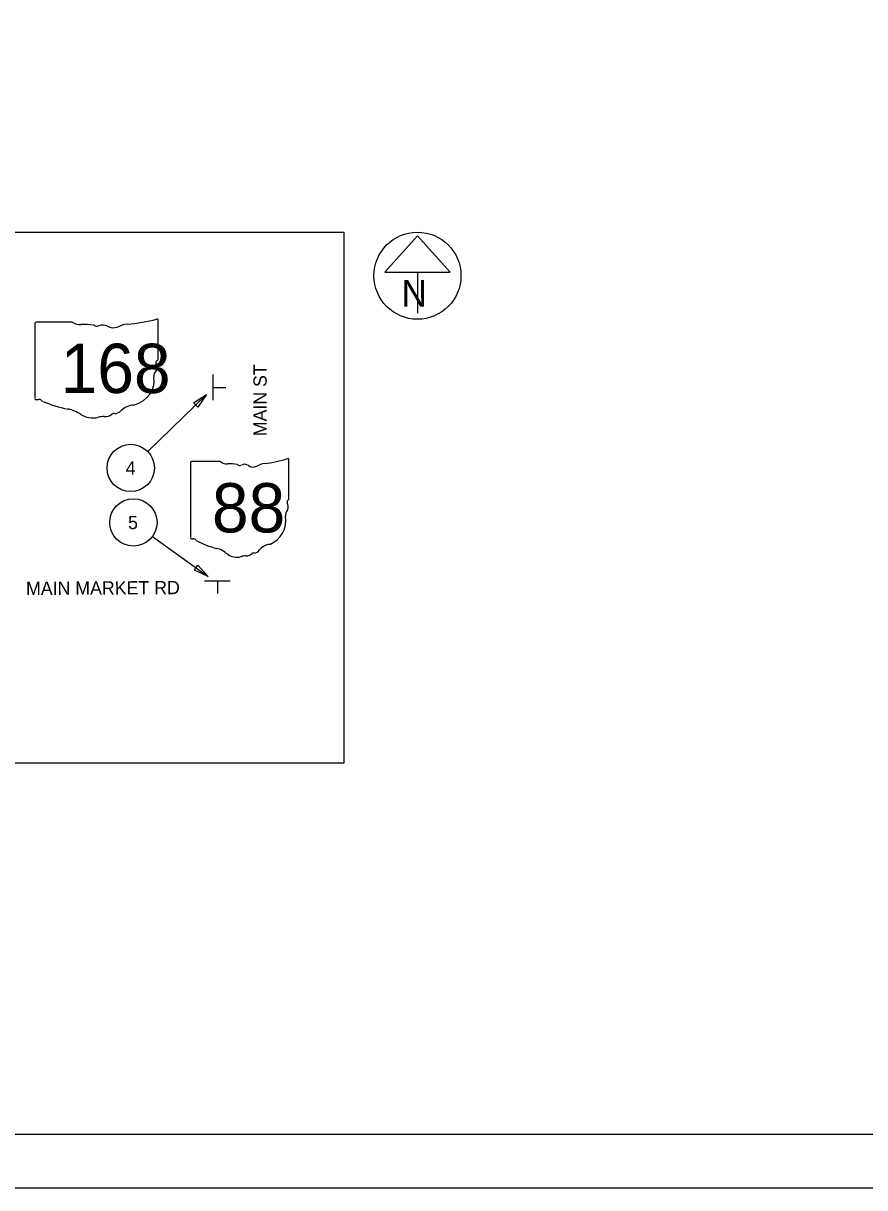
# Model space of a CAD drawing. Extents: x -0.3 to 34, y 0 to 22.
# Drawn here: x 18.15 to 26.07, y 0 to 10.97 of the extents above; entities that cross this region are included whole.
import ezdxf

# ---------------------------------------------------------------- set-up
doc = ezdxf.new("R2010")
doc.units = 0
for name, color, linetype in [('GM_X_Adjacent_County_Text', 7, 'Continuous'), ('GM_X_County', 7, 'Continuous'), ('GM_X_County_Subdivision', 7, 'Continuous'), ('GM_X_County_Subdivision_Text', 7, 'Continuous'), ('GM_X_Minor_River_Text', 7, 'Continuous'), ('GM_X_Section', 7, 'Continuous')]:
    doc.layers.add(name, color=color, linetype=linetype)

msp = doc.modelspace()

# ---------------------------------------------------------------- linework, layer by layer
at = {"layer": 'GM_X_Adjacent_County_Text'}
for p, q in [((21.86, 8.964), (21.552, 8.623)), ((22.168, 8.623), (21.86, 8.964)), ((21.552, 8.623), (22.168, 8.623)), ((21.86, 8.623), (21.86, 8.236)), ((19.32, 6.935), (19.872, 7.471)), ((19.365, 6.135), (19.889, 5.757))]:
    msp.add_line(p, q, dxfattribs=at)
for points in [[(16.167, 9), (21.167, 9), (21.167, 4), (16.167, 4)], [(19.791, 7.353), (19.752, 7.393), (19.872, 7.471)], [(19.759, 5.816), (19.792, 5.862), (19.889, 5.757)]]:
    msp.add_lwpolyline(points, close=True, dxfattribs=at)
for centre, radius in [((21.86, 8.59), 0.41), ((19.159, 6.779), 0.223), ((19.184, 6.266), 0.223)]:
    msp.add_circle(centre, radius, dxfattribs=at)
at = {"layer": 'GM_X_County'}
msp.add_lwpolyline([(1.5, 21.5), (33.5, 21.5), (33.5, 0.5), (1.5, 0.5)], close=True, dxfattribs=at)
at = {"layer": 'GM_X_County_Subdivision'}
for p, q in [((18.257, 8.139), (18.257, 7.435)), ((18.608, 8.152), (18.269, 8.152)), ((19.417, 7.8), (19.417, 8.169)), ((19.417, 7.801), (19.417, 7.8)), ((19.722, 6.827), (19.722, 6.123)), ((20.003, 6.839), (19.731, 6.839)), ((20.65, 6.488), (20.65, 6.857)), ((20.65, 6.488), (20.65, 6.488))]:
    msp.add_line(p, q, dxfattribs=at)
for centre, radius, start, end in [((19.733, 6.829), 0.0108, 98.1301, 188.1301), ((20.068, 6.921), 0.104, 231.6195, 271.1119), ((20.102, 6.444), 0.374, 80.4867, 94.9883), ((20.187, 6.832), 0.0301, 219.7921, 297.1024), ((20.232, 6.751), 0.0626, 54.4667, 119.1411), ((20.312, 6.863), 0.0753, 233.8562, 294.8282), ((20.445, 6.624), 0.198, 97.3462, 120.7689), ((20.32, 7.8), 0.984, 275.8445, 288.9065), ((20.64, 6.858), 0.0103, 351.8621, 97.738), ((20.648, 6.461), 0.016, 107.944, 210.337), ((20.639, 6.487), 0.0111, 289.6038, 7.7341), ((20.687, 6.334), 0.0698, 136.8065, 186.9296), ((20.546, 6.415), 0.096, 340.033, 23.6496), ((20.375, 6.287), 0.246, 292.3089, 8.9858), ((19.733, 6.121), 0.0108, 171.9584, 258.3066), ((19.735, 6.193), 0.0828, 267.339, 280.6039), ((19.751, 6.082), 0.0298, 29.7484, 93.2717), ((20.128, 6.715), 0.711, 240.4129, 257.1985), ((20.479, 5.925), 0.135, 94.4031, 142.5768), ((19.916, 5.806), 0.222, 47.1842, 75.836), ((20.157, 6.079), 0.141, 230.7004, 286.2918), ((20.239, 5.835), 0.116, 85.6951, 111.2099), ((20.249, 6.026), 0.0752, 268.777, 315.5493), ((20.317, 5.958), 0.0212, 65.7517, 132.6484), ((20.308, 6.054), 0.0795, 282.8732, 323.2771)]:
    msp.add_arc(centre, radius, start, end, dxfattribs=at)
for centre, major_axis, start_param, end_param in [((18.27, 8.141), (0.0134, 0), 1.712693, 3.28349), ((18.689, 8.233), (0.13, 0), 4.042523, 4.731795), ((18.732, 7.756), (0.468, 0), 1.404758, 1.657858), ((18.839, 8.145), (0.0376, 0), 3.836095, 5.185415), ((18.894, 8.063), (0.0782, 0), 0.950623, 2.079405), ((19.161, 7.936), (0.248, 0), 1.699011, 2.107814), ((19.004, 9.112), (1.23, 0), 4.814394, 5.042369), ((19.404, 8.171), (0.0129, 0), 6.141152, 7.989035), ((18.995, 8.175), (0.0941, 0), 4.081561, 5.145723), ((19.414, 7.773), (0.02, 0), 1.883978, 3.671073), ((19.403, 7.799), (0.0138, 0), 5.05454, 6.418171), ((19.463, 7.646), (0.0873, 0), 2.387724, 3.262537), ((19.287, 7.727), (0.12, 0), 5.934695, 6.695948), ((19.073, 7.599), (0.308, 0), 5.101752, 6.440018), ((18.27, 7.433), (0.0136, 0), 3.00124, 4.508301), ((18.273, 7.506), (0.103, 0), 4.665946, 4.897461), ((18.294, 7.394), (0.0373, 0), 0.519207, 1.627899), ((18.765, 8.027), (0.888, 0), 4.195997, 4.488961), ((19.203, 7.237), (0.169, 0), 1.647645, 2.488434), ((18.5, 7.119), (0.278, 0), 0.823519, 1.323587), ((18.801, 7.391), (0.176, 0), 4.026481, 4.996735), ((18.902, 7.147), (0.145, 0), 1.495662, 1.94098), ((18.915, 7.338), (0.094, 0), 4.691044, 5.507374), ((19, 7.27), (0.0265, 0), 1.147584, 2.315152), ((18.989, 7.367), (0.0994, 0), 4.937069, 5.64225)]:
    msp.add_ellipse(centre, major_axis=major_axis, ratio=0.8, start_param=start_param, end_param=end_param, dxfattribs=at)
at = {"layer": 'GM_X_County_Subdivision_Text'}
msp.add_circle((21.86, 8.59), 0.41, dxfattribs=at)
at = {"layer": 'GM_X_Minor_River_Text'}
for p, q in [((19.935, 7.418), (19.935, 7.658)), ((19.935, 7.538), (20.055, 7.538)), ((19.855, 5.717), (20.095, 5.717)), ((19.975, 5.717), (19.975, 5.597))]:
    msp.add_line(p, q, dxfattribs=at)
at = {"layer": 'GM_X_Section'}
msp.add_lwpolyline([(0, 0), (34, 0), (34, 22), (0, 22)], close=True, dxfattribs=at)

# ---------------------------------------------------------------- texts
at = {"layer": 'GM_X_Adjacent_County_Text'}
for s, height, p in [('N', 0.25, (21.709, 8.299)), ('4', 0.125, (19.112, 6.717)), ('5', 0.125, (19.134, 6.203))]:
    msp.add_text(s, height=height, dxfattribs=at).set_placement(p)
for s, rotation, p in [('MAIN ST', 90, (20.44, 7.078)), ('MAIN MARKET RD', 0.3376, (18.173, 5.582))]:
    msp.add_text(s, height=0.125, rotation=rotation, dxfattribs=at).set_placement(p)
at = {"layer": 'GM_X_County_Subdivision'}
for s, p in [('168', (18.499, 7.485)), ('88', (19.924, 6.172))]:
    msp.add_text(s, height=0.4641, dxfattribs=at).set_placement(p)

doc.saveas('drawing.dxf')
